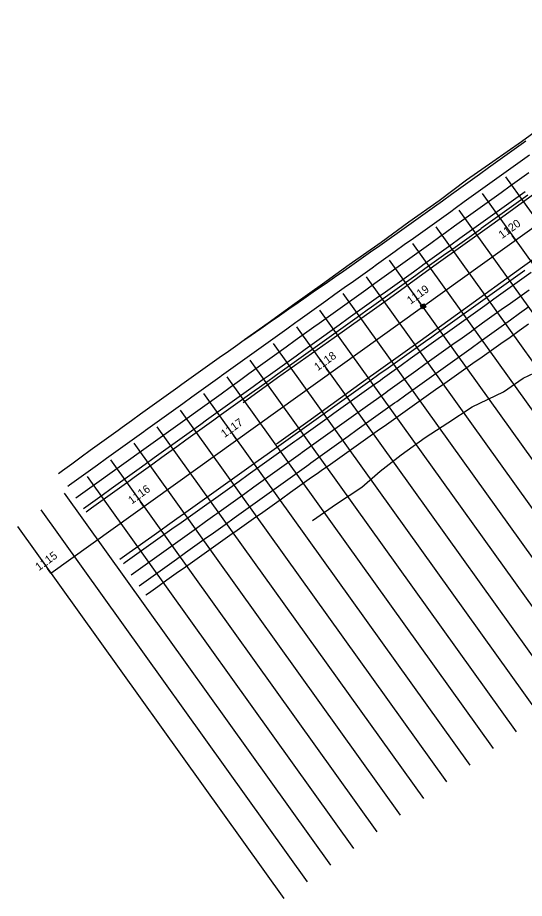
# Model space of a CAD drawing. Extents: x -354 to 8821, y -19535 to 19639.
# Drawn here: x 7369 to 7812, y 1423 to 2193 of the extents above; entities that cross this region are included whole.
import ezdxf

# ---------------------------------------------------------------- set-up
doc = ezdxf.new("R2010")
doc.units = 0
for name, color, linetype in [('DR_X_Cells', 7, 'Continuous'), ('GK_Drainage_Nodes', 7, 'Continuous'), ('PV_X_COP', 7, 'Continuous'), ('PV_X_EOP', 7, 'Continuous'), ('PV_X_Shoulder_Aggregate', 7, 'Continuous'), ('RW_X_CL_50', 7, 'Continuous'), ('SC_Scratch1', 7, 'Continuous'), ('SV_X_Top_of_Bank', 7, 'Continuous')]:
    doc.layers.add(name, color=color, linetype=linetype)

msp = doc.modelspace()

# ---------------------------------------------------------------- linework, layer by layer
at = {"layer": 'DR_X_Cells'}
for p, q in [((7722.13, 1940.52), (7722.36, 1941.38)), ((7722.69, 1939.54), (7723.34, 1941.94)), ((7723.48, 1939.38), (7724.1, 1941.69)), ((7724.46, 1939.94), (7724.66, 1940.71))]:
    msp.add_line(p, q, dxfattribs=at)
for points in [[(7721.1, 1941.26), (7723.99, 1942.92), (7725.66, 1940.03), (7722.77, 1938.37)], [(7721.82, 1941.07), (7723.8, 1942.21), (7724.94, 1940.22), (7722.96, 1939.08)], [(7722.01, 1941.01), (7723.75, 1942.01), (7724.75, 1940.28), (7723.01, 1939.28)]]:
    msp.add_lwpolyline(points, close=True, dxfattribs=at)
at = {"layer": 'GK_Drainage_Nodes'}
for p, q in [((7722.55, 1942.09), (7722.55, 1942.09)), ((7722.88, 1941.51), (7722.88, 1941.51)), ((7724.25, 1941.14), (7724.25, 1941.14)), ((7722.51, 1940.15), (7722.51, 1940.15)), ((7723.38, 1940.65), (7723.38, 1940.65)), ((7723.38, 1940.65), (7723.38, 1940.65)), ((7723.38, 1940.65), (7723.38, 1940.65)), ((7723.88, 1939.78), (7723.88, 1939.78)), ((7724.21, 1939.2), (7724.21, 1939.2))]:
    msp.add_line(p, q, dxfattribs=at)
at = {"layer": 'PV_X_COP'}
for points in [[(7419.61, 1773.07), (7427.73, 1778.91), (7435.85, 1784.74), (7443.97, 1790.58), (7445.24, 1791.5), (7453.36, 1797.33), (7461.48, 1803.17), (7469.6, 1809), (7470.88, 1809.92), (7479, 1815.75), (7487.12, 1821.59), (7495.25, 1827.42), (7496.52, 1828.34), (7504.64, 1834.17), (7512.77, 1840), (7520.89, 1845.83), (7522.16, 1846.75), (7522.16, 1846.75), (7530.29, 1852.58), (7538.41, 1858.41), (7546.54, 1864.24), (7554.66, 1870.07), (7562.78, 1875.9), (7570.91, 1881.74), (7579.03, 1887.57), (7587.15, 1893.4), (7595.28, 1899.23), (7603.4, 1905.07), (7611.52, 1910.9), (7619.65, 1916.73), (7627.77, 1922.56), (7632.47, 1925.94), (7640.59, 1931.77), (7648.71, 1937.6), (7656.84, 1943.44), (7664.96, 1949.27), (7673.08, 1955.1), (7681.2, 1960.94), (7689.33, 1966.77), (7697.45, 1972.6), (7705.57, 1978.44), (7713.69, 1984.27), (7721.81, 1990.11), (7729.94, 1995.94), (7738.06, 2001.77), (7742.76, 2005.15), (7750.88, 2010.99), (7759, 2016.82), (7767.12, 2022.66), (7775.24, 2028.49), (7783.36, 2034.33), (7791.49, 2040.16), (7799.61, 2046), (7807.73, 2051.83), (7815.85, 2057.67)], [(7468.05, 1705.7), (7476.18, 1711.53), (7484.3, 1717.36), (7492.43, 1723.18), (7500.56, 1729.01), (7508.68, 1734.84), (7516.81, 1740.67), (7524.94, 1746.49), (7533.06, 1752.32), (7541.19, 1758.15), (7542.85, 1759.34), (7550.97, 1765.16), (7559.1, 1770.99), (7567.23, 1776.82), (7575.35, 1782.64), (7583.48, 1788.47), (7591.61, 1794.3), (7599.74, 1800.13), (7607.86, 1805.95), (7615.99, 1811.78), (7617.65, 1812.97), (7625.77, 1818.8), (7633.9, 1824.62), (7642.03, 1830.45), (7650.16, 1836.28), (7658.28, 1842.1), (7666.41, 1847.93), (7674.54, 1853.76), (7682.66, 1859.58), (7690.79, 1865.41), (7692.45, 1866.6), (7700.58, 1872.43), (7708.7, 1878.25), (7716.83, 1884.08), (7724.96, 1889.91), (7733.08, 1895.73), (7741.21, 1901.56), (7749.34, 1907.39), (7757.47, 1913.21), (7765.59, 1919.04), (7767.25, 1920.23), (7767.25, 1920.23), (7775.38, 1926.05), (7783.51, 1931.88), (7791.63, 1937.71), (7799.76, 1943.53), (7807.89, 1949.36), (7816.02, 1955.18)]]:
    msp.add_lwpolyline(points, dxfattribs=at)
at = {"layer": 'PV_X_EOP'}
for points in [[(7816.26, 2072.67), (7808.13, 2066.85), (7800.01, 2061.02), (7791.88, 2055.19), (7783.76, 2049.36), (7775.63, 2043.54), (7767.5, 2037.71), (7759.37, 2031.88), (7751.24, 2026.06), (7747.5, 2023.38)], [(7426.21, 1763.89), (7434.33, 1769.72), (7442.45, 1775.56), (7450.57, 1781.4), (7458.69, 1787.23), (7466.81, 1793.07), (7474.93, 1798.9), (7480.04, 1802.57), (7488.16, 1808.41), (7496.29, 1814.24), (7504.41, 1820.07), (7512.53, 1825.91), (7520.65, 1831.74), (7528.78, 1837.57), (7533.89, 1841.24), (7542.01, 1847.07), (7550.14, 1852.9), (7558.26, 1858.73), (7566.39, 1864.56), (7574.51, 1870.39), (7582.64, 1876.21), (7587.75, 1879.88), (7595.88, 1885.71), (7604.01, 1891.53), (7612.13, 1897.36), (7620.26, 1903.18), (7628.39, 1909.01), (7636.52, 1914.83), (7641.63, 1918.5), (7641.63, 1918.5), (7649.76, 1924.32), (7657.89, 1930.14), (7666.02, 1935.97), (7674.15, 1941.79), (7682.27, 1947.62), (7690.4, 1953.44), (7698.53, 1959.27), (7706.66, 1965.1), (7714.78, 1970.92), (7722.91, 1976.75), (7723.07, 1976.87), (7731.2, 1982.69), (7739.33, 1988.52), (7747.45, 1994.35), (7755.58, 2000.18), (7763.7, 2006.01), (7771.83, 2011.84), (7779.95, 2017.66), (7788.08, 2023.49), (7796.2, 2029.32), (7804.33, 2035.16), (7804.49, 2035.27), (7812.61, 2041.1)], [(7747.5, 2023.38), (7739.38, 2017.55), (7731.25, 2011.73), (7723.12, 2005.91), (7714.99, 2000.08), (7706.86, 1994.26), (7698.73, 1988.44), (7690.6, 1982.62), (7682.46, 1976.8), (7678.72, 1974.12), (7678.72, 1974.12), (7670.59, 1968.3), (7662.46, 1962.48), (7654.33, 1956.66), (7646.2, 1950.83), (7638.07, 1945.01), (7629.94, 1939.19), (7621.81, 1933.36), (7613.68, 1927.54), (7612.11, 1926.41), (7603.98, 1920.59), (7595.85, 1914.76), (7587.72, 1908.93), (7579.6, 1903.11), (7571.47, 1897.28), (7563.34, 1891.45), (7555.22, 1885.62), (7547.09, 1879.8), (7545.52, 1878.67), (7537.39, 1872.84), (7529.27, 1867.01), (7521.14, 1861.18), (7513.02, 1855.35), (7504.9, 1849.51), (7496.77, 1843.68), (7488.65, 1837.85), (7480.53, 1832.02), (7478.95, 1830.89), (7470.83, 1825.05), (7462.71, 1819.22), (7454.59, 1813.38), (7446.47, 1807.55), (7438.35, 1801.71), (7430.23, 1795.88), (7422.11, 1790.04), (7413.99, 1784.2), (7412.42, 1783.07)], [(7817.81, 1970.32), (7809.68, 1964.5), (7801.55, 1958.67), (7793.43, 1952.84), (7785.3, 1947.02), (7777.17, 1941.19), (7769.04, 1935.37)], [(7769.04, 1935.37), (7760.91, 1929.53), (7760.91, 1929.53), (7752.78, 1923.71), (7744.65, 1917.88), (7736.52, 1912.06), (7728.39, 1906.23), (7720.26, 1900.41), (7712.13, 1894.59), (7704, 1888.77), (7695.87, 1882.94), (7687.74, 1877.12), (7686.02, 1875.9), (7677.89, 1870.08), (7669.76, 1864.26), (7661.62, 1858.44), (7653.49, 1852.62), (7645.35, 1846.81), (7637.22, 1840.99), (7629.08, 1835.18), (7620.95, 1829.37), (7612.81, 1823.55), (7611.09, 1822.33), (7602.95, 1816.51), (7594.82, 1810.7), (7586.68, 1804.89), (7578.54, 1799.08), (7570.4, 1793.27), (7562.26, 1787.47), (7554.12, 1781.66), (7545.97, 1775.85), (7537.83, 1770.05), (7536.11, 1768.82), (7527.97, 1763.02), (7519.83, 1757.21), (7511.68, 1751.41), (7503.54, 1745.61), (7495.39, 1739.81), (7487.25, 1734.01), (7479.1, 1728.21), (7470.95, 1722.41), (7462.81, 1716.61), (7461.09, 1715.39)], [(7474.94, 1696.12), (7483.07, 1701.94), (7491.2, 1707.76), (7499.33, 1713.58), (7507.46, 1719.41), (7515.59, 1725.23), (7523.72, 1731.05), (7531.85, 1736.87), (7539.98, 1742.69), (7548.11, 1748.52), (7550.03, 1749.89), (7558.16, 1755.71), (7566.29, 1761.53), (7574.42, 1767.36), (7582.55, 1773.18), (7590.68, 1779), (7598.81, 1784.83), (7606.94, 1790.65), (7615.07, 1796.47), (7623.2, 1802.3), (7625.11, 1803.67), (7633.24, 1809.49), (7641.37, 1815.32), (7649.5, 1821.14), (7657.63, 1826.96), (7665.76, 1832.79), (7673.89, 1838.61), (7682.01, 1844.44), (7690.14, 1850.26), (7698.27, 1856.09), (7700.19, 1857.46), (7708.31, 1863.29), (7716.44, 1869.11), (7724.57, 1874.94), (7732.7, 1880.76), (7740.83, 1886.59), (7748.95, 1892.41), (7757.08, 1898.24), (7765.21, 1904.07), (7773.34, 1909.89), (7775.25, 1911.27), (7775.25, 1911.27), (7783.38, 1917.09), (7791.51, 1922.92), (7799.63, 1928.75), (7807.76, 1934.57), (7815.89, 1940.4)]]:
    msp.add_lwpolyline(points, dxfattribs=at)
at = {"layer": 'PV_X_Shoulder_Aggregate'}
for points in [[(8427.82, 2473.88), (8377.92, 2438.43), (8325.47, 2400.65), (8273.79, 2363.79), (8221.55, 2326.85), (8180.8, 2297.81), (8128.12, 2260.38), (8082.15, 2226.78), (8028.58, 2188.39), (7978.98, 2152.72), (7933.92, 2120.35), (7882.32, 2083.22), (7833.79, 2048.53), (7785.45, 2013.27), (7732.67, 1975.86), (7693.88, 1947.56), (7645.37, 1913.17), (7595.97, 1878.05), (7566.01, 1856.18)], [(8455.97, 2436.7), (8404.42, 2400.06), (8350.84, 2361.5), (8300.75, 2325.62), (8248.8, 2287.69), (8207.76, 2258.6), (8155.02, 2221.78), (8108.79, 2189.02), (8054.7, 2149.69), (8004.91, 2114.31), (7957.66, 2080.83), (7908.19, 2045.16), (7859.18, 2009.79), (7810.29, 1974.92), (7758.63, 1937.48), (7720.6, 1910.02), (7671.27, 1875.01), (7622.48, 1839.57), (7594.92, 1820.15)], [(7567.11, 1911.52), (7587.72, 1926.23), (7611.09, 1942.98), (7635.25, 1960.24), (7658.76, 1977.17), (7686.58, 1996.61), (7710.89, 2014.6), (7737.3, 2033.21), (7761.39, 2051.3), (7784.44, 2067.14), (7809.27, 2084.75), (7836.64, 2104.72), (7860.22, 2121.36), (7882.91, 2137.69), (7906.5, 2154.55), (7929.27, 2170.9), (7954.98, 2189.24), (7981.71, 2208.24)], [(7813.05, 2085.07), (7804.94, 2079.21), (7796.84, 2073.36), (7788.73, 2067.5), (7780.63, 2061.64), (7772.62, 2055.86), (7772.62, 2055.86), (7764.51, 2050.01), (7756.39, 2044.17), (7748.27, 2038.33), (7740.14, 2032.51), (7733.19, 2027.54)], [(7814.82, 2037.7), (7806.7, 2031.87), (7798.57, 2026.05), (7790.44, 2020.22), (7782.31, 2014.39), (7774.19, 2008.57), (7773.71, 2008.23), (7765.58, 2002.4)], [(7733.19, 2027.54), (7725.05, 2021.73), (7716.91, 2015.93), (7708.76, 2010.14), (7700.6, 2004.35), (7693.63, 1999.42), (7685.46, 1993.65), (7677.28, 1987.89), (7669.1, 1982.14), (7660.92, 1976.4), (7653.92, 1971.5), (7645.72, 1965.78), (7637.52, 1960.06), (7629.31, 1954.35), (7621.1, 1948.64), (7614.08, 1943.78), (7614.08, 1943.78), (7605.86, 1938.09), (7597.64, 1932.38), (7589.44, 1926.67), (7581.24, 1920.95), (7573.04, 1915.22), (7564.85, 1909.48), (7561.26, 1906.95), (7553.08, 1901.2), (7544.91, 1895.44), (7536.74, 1889.66), (7528.58, 1883.88), (7520.43, 1878.09), (7512.28, 1872.3), (7508.71, 1869.75), (7500.57, 1863.93), (7492.44, 1858.11), (7484.31, 1852.28), (7476.2, 1846.44), (7468.08, 1840.6), (7459.98, 1834.74), (7456.42, 1832.17), (7448.33, 1826.3), (7440.24, 1820.42), (7432.15, 1814.53), (7424.08, 1808.63), (7416.01, 1802.73), (7407.94, 1796.81), (7404.41, 1794.21)], [(7765.58, 2002.4), (7757.45, 1996.58), (7749.32, 1990.75), (7741.19, 1984.93), (7733.06, 1979.11), (7724.93, 1973.29), (7716.8, 1967.46), (7708.67, 1961.64), (7700.54, 1955.82), (7692.41, 1950), (7684.28, 1944.18), (7676.14, 1938.36), (7675.67, 1938.02), (7667.54, 1932.2), (7659.4, 1926.38), (7651.27, 1920.57), (7643.13, 1914.75), (7635, 1908.93), (7626.87, 1903.12), (7618.73, 1897.3), (7610.6, 1891.49), (7602.46, 1885.67), (7594.32, 1879.86), (7586.19, 1874.04), (7578.05, 1868.23), (7577.57, 1867.89), (7577.57, 1867.89), (7569.44, 1862.08), (7561.3, 1856.26), (7553.17, 1850.44), (7545.05, 1844.61), (7540.25, 1841.17), (7532.12, 1835.34), (7524, 1829.51), (7515.88, 1823.67), (7507.77, 1817.83), (7502.98, 1814.38), (7494.87, 1808.53), (7486.76, 1802.68), (7478.65, 1796.83), (7470.54, 1790.97), (7465.76, 1787.51), (7457.66, 1781.65), (7449.56, 1775.78), (7441.47, 1769.91), (7433.37, 1764.03), (7428.6, 1760.57)], [(7458.07, 1719.58), (7466.22, 1725.38), (7471.99, 1729.49), (7480.14, 1735.29), (7485.91, 1739.4), (7494.06, 1745.2), (7499.83, 1749.32), (7507.98, 1755.12), (7513.75, 1759.23), (7513.75, 1759.23), (7521.89, 1765.03), (7530.04, 1770.84), (7538.18, 1776.64), (7546.32, 1782.45), (7554.47, 1788.25), (7562.61, 1794.05), (7570.75, 1799.86), (7578.89, 1805.67), (7587.03, 1811.47), (7595.18, 1817.28), (7603.32, 1823.08), (7611.46, 1828.89), (7619.6, 1834.7), (7627.74, 1840.5), (7635.88, 1846.31), (7644.02, 1852.12), (7652.16, 1857.93), (7660.3, 1863.73), (7668.44, 1869.54), (7676.58, 1875.35), (7684.72, 1881.16), (7692.86, 1886.97), (7701, 1892.78), (7709.14, 1898.59), (7717.28, 1904.4), (7725.42, 1910.21), (7730.81, 1914.06), (7738.95, 1919.88), (7747.09, 1925.69), (7755.23, 1931.5), (7763.37, 1937.31), (7771.5, 1943.12), (7779.64, 1948.94), (7787.78, 1954.75), (7795.91, 1960.56), (7804.05, 1966.37), (7812.19, 1972.19)], [(7815.44, 1924.9), (7807.29, 1919.1), (7799.35, 1913.46), (7791.19, 1907.69), (7783.23, 1902.07), (7775.06, 1896.3)], [(7775.06, 1896.3), (7766.89, 1890.54), (7758.72, 1884.77), (7750.55, 1879.01), (7742.38, 1873.24), (7734.21, 1867.47), (7726.04, 1861.7), (7717.88, 1855.93), (7709.71, 1850.16), (7707.56, 1848.64), (7699.39, 1842.87), (7691.23, 1837.09), (7683.06, 1831.32), (7674.9, 1825.55), (7666.73, 1819.77), (7658.57, 1814), (7650.41, 1808.22), (7642.24, 1802.44), (7634.08, 1796.66), (7631.93, 1795.14), (7623.77, 1789.36), (7615.61, 1783.58), (7607.45, 1777.8), (7599.29, 1772.02), (7591.13, 1766.24), (7582.97, 1760.45), (7574.82, 1754.67), (7566.66, 1748.88), (7558.5, 1743.1), (7556.35, 1741.57), (7548.2, 1735.79), (7540.04, 1730), (7531.89, 1724.21), (7523.73, 1718.42), (7515.58, 1712.63), (7507.43, 1706.84), (7499.27, 1701.05), (7491.12, 1695.26), (7482.97, 1689.47), (7480.82, 1687.94)]]:
    msp.add_lwpolyline(points, dxfattribs=at)
at = {"layer": 'RW_X_CL_50'}
for p, q in [((7397.71, 1707.37), (8616.98, 2581.09)), ((7804.14, 1998.61), (7801.22, 2002.67)), ((7722.85, 1940.36), (7719.94, 1944.43)), ((7641.57, 1882.11), (7638.65, 1886.18)), ((7560.28, 1823.86), (7557.37, 1827.93)), ((7479, 1765.62), (7476.09, 1769.68)), ((7397.71, 1707.37), (7394.8, 1711.43))]:
    msp.add_line(p, q, dxfattribs=at)
at = {"layer": 'SC_Scratch1'}
for p, q in [((7795.33, 2053.81), (8028.33, 1728.68)), ((7775.01, 2039.25), (8008, 1714.11)), ((7754.69, 2024.69), (7987.68, 1699.55)), ((7734.37, 2010.13), (7967.36, 1684.99)), ((7714.05, 1995.57), (7947.04, 1670.43)), ((7693.73, 1981), (7926.72, 1655.87)), ((7673.41, 1966.44), (7906.4, 1641.3)), ((7653.08, 1951.88), (7886.08, 1626.74)), ((7632.76, 1937.32), (7865.76, 1612.18)), ((7612.44, 1922.75), (7845.44, 1597.62)), ((7592.12, 1908.19), (7825.12, 1583.06)), ((7571.8, 1893.63), (7804.79, 1568.49)), ((7551.48, 1879.07), (7784.47, 1553.93)), ((7531.16, 1864.51), (7764.15, 1539.37)), ((7510.84, 1849.94), (7743.83, 1524.81)), ((7490.52, 1835.38), (7723.51, 1510.25)), ((7470.2, 1820.82), (7703.19, 1495.68)), ((7449.87, 1806.26), (7682.87, 1481.12)), ((7429.55, 1791.7), (7662.55, 1466.56)), ((7409.23, 1777.13), (7642.23, 1452)), ((7388.91, 1762.57), (7621.9, 1437.43)), ((7368.59, 1748.01), (7601.58, 1422.87))]:
    msp.add_line(p, q, dxfattribs=at)
at = {"layer": 'SV_X_Top_of_Bank'}
msp.add_lwpolyline([(7626.41, 1753.44), (7647.56, 1767.93), (7669.59, 1782.51), (7685.68, 1796.37), (7704.24, 1810.87), (7725.17, 1825.82), (7744.88, 1838.79), (7766.3, 1852.78), (7793.61, 1865.75), (7810.76, 1877.69), (7830.68, 1887.08)], dxfattribs=at)

# ---------------------------------------------------------------- texts
at = {"layer": 'RW_X_CL_50'}
for s, p in [('1120', (7792.4, 1999.43)), ('1119', (7712.3, 1942.03)), ('1118', (7631.11, 1883.85)), ('1117', (7549.58, 1825.42)), ('1116', (7468.41, 1767.25)), ('1115', (7387.15, 1709.02))]:
    msp.add_text(s, height=7, rotation=35.62538, dxfattribs=at).set_placement(p)

doc.saveas('drawing.dxf')
